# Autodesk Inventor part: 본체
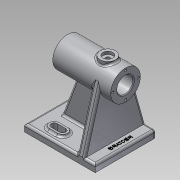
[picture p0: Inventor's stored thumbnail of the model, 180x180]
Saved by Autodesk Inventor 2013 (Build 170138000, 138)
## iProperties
Created: 2019-10
Part Number: 본체
Material: 알루미늄 6061
Document SubType Name: Modeling
Designer: hana-max10
Density: 2.71 g/cm^3
Mass: 588.817 g
Surface Area: 544.414 cm^2
Volume: 217.276 cm^3
Author: hana-max10
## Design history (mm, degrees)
sketch "스케치1"
  geometry: L1 (-47.727, 63.797)-(52.273, 63.797); L2 (52.273, 63.797)-(52.273, -22.203); L3 (52.273, -22.203)-(-47.727, -22.203); L4 (-47.727, -22.203)-(-47.727, 63.797); 1 further point
  constraints: 8 end point, 2 parallel, 1 horizontal, 1 perpendicular
  dimensions: "d0" = 100 distance of L2.end L3.end; "d2" = 86 distance of L1.end L2.end
extrude "돌출1" new body sketch "스케치1" distance "d3" = 10; taper "d4" = 0 deg
node "작업 평면1"
sketch "스케치2"
  geometry: L1 (52.273, 63.797)-(-47.727, 63.797) reference; L2 (-47.727, 63.797)-(-47.727, -22.203) reference; L3 (-47.727, -22.203)-(52.273, -22.203) reference; L4 (52.273, -22.203)-(52.273, 63.797) reference; L5 (-47.727, 20.797)-(111.797, 20.797); L6 (52.273, 41.797)-(-29.727, 41.797); L7 (-29.727, 41.797)-(-29.727, 35.297); L8 (-29.727, 35.297)-(32.273, 35.297); L9 (32.273, 35.297)-(32.273, 32.297); L10 (32.273, 32.297)-(52.273, 32.297); L11 (52.273, 32.297)-(52.273, 41.797); 1 further point
  constraints: 14 end point, 4 horizontal, 3 vertical, 1 midpoint
  dimensions: "d6" = 82 distance of L6.start L6.end; "d8" = 9.5 distance of L10.end L6.start; "d9" = 6.5 distance of L6.end L7.end; "d10" = 62 distance of L7.end L8.end; "d11" = 23 diameter of L10 L5; "d12" = 0 distance between parallel lines of L4 L11
revolve "회전1" sketch "스케치2" stored, may be unused: angle "d13" = 90 deg
node "작업 평면2"
sketch "스케치3"
  geometry: L1 (47.727, 0)-(47.727, 10) reference; L2 (32.727, 10)-(-27.273, 10); L3 (-27.273, 10)-(-27.273, 67); L4 (-27.273, 67)-(11.981, 67); L5 (11.981, 67)-(32.727, 10); L6 (-52.273, 0)-(-52.273, 10) reference; L7 (47.727, 10)-(-52.273, 10) reference; L8 (-52.273, 107)-(-52.273, 65) reference; L9 (29.727, 107)-(29.727, 65) reference; 1 further point
  constraints: 8 end point, 2 horizontal, 1 vertical
  dimensions: "d19" = 70 deg angle of L2 L5; "d20" = 15 distance from line of L1 L2.start; "d21" = 25 distance between parallel lines of L6 L3; "d22" = 0 distance between parallel lines of L7 L2; "d23" = 57 distance of L2.end L3.end
extrude "돌출2" join sketch "스케치3" stored distance "d24" = 10; taper "d25" = 0 deg
sketch "스케치4"
  geometry: L1 (0, 0)-(-55.555, 0) reference; L2 (-55.655, 10)-(0, 10) reference; L3 (-81.642, -15.431)-(0, -38.203); L4 (0, -38.203)-(0, 47.797); L5 (0, 47.797)-(-81.642, 25.025); L6 (0, -38.203)-(0, 47.797) reference; L7 (-76, 4.797)-(20.74, 4.797); A1 r 21 centre (-76, 4.797) between (-55.555, 0) and (-55.655, 10) reference; A2 r 21 centre (-76, 4.797) between (-55.655, 10) and (-55.555, 0) reference; A3 r 21 centre (-76, 4.797) between (-81.642, -15.431) and (-81.642, 25.025); 1 further point
  constraints: 8 end point, 3 point on circle, 2 tangent, 1 centre point, 1 coincident, 1 horizontal, 1 vertical, 1 other
  dimensions: "d26" = 0 distance between parallel lines of L4 L6; "d27" = 86 distance of L3.end L4.end
extrude "돌출3" join sketch "스케치4" distance "d28" = 10; taper "d29" = 0 deg
node "작업 평면3"
sketch "스케치5"
  geometry: L1 (-21.727, 52.297)-(-9.727, 52.297); L2 (-21.727, 43.297)-(-9.727, 43.297); L3 (27.273, 63.797)-(-47.727, 63.797) reference; L4 (-47.727, 63.797)-(-47.727, -22.203) reference; L5 (27.273, 16)-(-32.727, 16) reference; L6 (-32.727, 26)-(27.273, 26) reference; L7 (-32.727, 16)-(-32.727, 26) reference; L8 (-32.727, 21)-(62.617, 21); L9 (-47.727, -21.797)-(-47.727, 64.203); L10 (-21.727, 54.797)-(-9.727, 54.797); L11 (-21.727, 40.797)-(-9.727, 40.797); A1 r 4.5 centre (-21.727, 47.797) between (-21.727, 52.297) and (-21.727, 43.297); A2 r 4.5 centre (-9.727, 47.797) between (-9.727, 43.297) and (-9.727, 52.297); A3 r 7 centre (-9.727, 47.797) between (-9.727, 40.797) and (-9.727, 54.797); A4 r 7 centre (-21.727, 47.797) between (-21.727, 54.797) and (-21.727, 40.797)
  constraints: 12 end point, 8 point on circle, 7 tangent, 4 centre point, 2 coincident, 2 symmetric about line, 1 horizontal, 1 midpoint, 1 parallel
  dimensions: "d31" = 9 diameter of A1; "d33" = 9 diameter of A2; "d34" = 16 distance from line of L3 A1.centre; "d35" = 26 distance from line of L4 A1.centre; "d36" = 12 distance of A2.centre A1.centre; "d37" = 16 distance from line of L3 A2.centre; "d39" = 14 diameter of A3; "d41" = 7 radius of A4
extrude "돌출4" join sketch "스케치5" distance "d42" = 3; taper "d43" = 0 deg
sketch "스케치6" dims "d61" = 10
  geometry: L1 (-21.727, 52.297)-(-9.727, 52.297); L2 (-21.727, 43.297)-(-9.727, 43.297); L3 (27.273, 63.797)-(-47.727, 63.797) reference; L4 (-47.727, 63.797)-(-47.727, -22.203) reference; L5 (-21.727, -1.703)-(-9.727, -1.703); L6 (-21.727, -10.703)-(-9.727, -10.703); A1 r 4.5 centre (-21.727, 47.797) between (-21.727, 52.297) and (-21.727, 43.297); A2 r 4.5 centre (-9.727, 47.797) between (-9.727, 43.297) and (-9.727, 52.297); A3 r 4.5 centre (-9.727, -6.203) between (-9.727, -10.703) and (-9.727, -1.703); A4 r 4.5 centre (-21.727, -6.203) between (-21.727, -1.703) and (-21.727, -10.703); 1 further point
  constraints: 8 end point, 8 point on circle, 4 centre point, 3 tangent, 1 parallel, 1 vertical, 10 other
  dimensions: "d44" = 12 distance of A2.centre A1.centre; "d46" = 9 diameter of A2; "d47" = 9 diameter of A1; "d48" = 16 distance from line of A1.centre L3; "d49" = 26 distance from line of L4 A1.centre; "d50" = 16 distance from line of L3 A2.centre; "d58" = 54 distance of L1.start L5.start
extrude "돌출5" cut sketch "스케치6" stored distance "d51" = 3; taper "d52" = 0 deg
fillet "모깎기1" dims "d63" = 3
fillet "모깎기2" dims "d64" = 3
chamfer "모따기1" distance "d65" = 1; stored, may be unused: second distance "d66" = 2, angle "d67" = 45 deg
fillet "모깎기3" dims "d68" = 3
fillet "모깎기4" dims "d69" = 3
node "작업 평면4"
sketch "스케치9"
  geometry: L1 (-52.273, 41.797)-(-52.273, -0.203) reference; L2 (-52.273, 20.797)-(59.849, 20.797); C1 r 11 at (-27.273, 20.797); 2 further points
  constraints: 2 end point, 1 centre point, 1 coincident, 1 horizontal, 1 midpoint, 1 point on line
  dimensions: "d71" = 22 diameter of C1; "d73" = 25 distance from line of L1 C1.centre
extrude "돌출6" join sketch "스케치9" stored distance "d74" = 3; taper "d75" = 0 deg
fillet "모깎기5" dims "d76" = 3
sketch "스케치11"
  geometry: A1 r 11 centre (27.273, 20.797) between (38.273, 20.797) and (16.273, 20.797) reference; 2 further points
  constraints: 1 coincident
hole "구멍1" sketch "스케치11" at (27.273, 20.797) diameter "d77" = 6; stored, may be unused: countersink angle "d81" = 90 deg, drill point angle "d83" = 118 deg; dims "d78" = 6, "d79" = 14, "d80" = 4, "d82" = 20
sketch "스케치12"
  geometry: L1 (40.684, 1.326)-(40.684, 42.805); L2 (40.684, 42.805)-(46.688, 42.805); L3 (46.688, 42.805)-(46.688, 1.326); L4 (46.688, 1.326)-(40.684, 1.326); 1 further point
  constraints: 2 other
feature "엠보싱1" sketch "스케치12" dims "d0" = 100, "d2" = 86, "d13" = 90 deg, "d84" = 0.5, "d85" = 0
sketch "스케치13" dims "d86" = 36
  geometry: L1 (18, 0)-(0, 0); C1 r 15.5 at (0, 0) reference; 2 further points
  constraints: 2 coincident, 2 end point, 1 horizontal, 1 horizontal alignment, 2 other
hole "구멍2" sketch "스케치13" at (18, 0) diameter "d88" = 3.242; stored, may be unused: countersink angle "d92" = 90 deg, drill point angle "d94" = 118 deg; dims "d89" = 6, "d90" = 14, "d91" = 4, "d93" = 8
sketch "스케치14" dims "d19" = 70 deg, "d20" = 15, "d21" = 25, "d22" = 0, "d23" = 57, "d99" = 36
  geometry: L1 (0, 0)-(-18, 0); C1 r 12.5 at (0, 0) reference; 2 further points
  constraints: 2 coincident, 2 end point, 1 horizontal, 1 horizontal alignment, 2 other
hole "구멍3" sketch "스케치14" at (-18, 0) diameter "d100" = 3.242; stored, may be unused: countersink angle "d104" = 90 deg, drill point angle "d106" = 118 deg; dims "d21" = 25, "d101" = 6, "d102" = 14, "d103" = 4, "d105" = 8
node "솔리드1"
pattern_linear "직사각형 패턴1" dims "d55" = 54
pattern_circular "원형 패턴1" dims angle "d96" = 360 deg
pattern_circular "원형 패턴2" dims angle "d108" = 360 deg
node "투영된 루프1"
node "투영된 루프2"
other parameters: "d5" = 76, "d14" = 21, "d30" = 3, "d38" = 14
